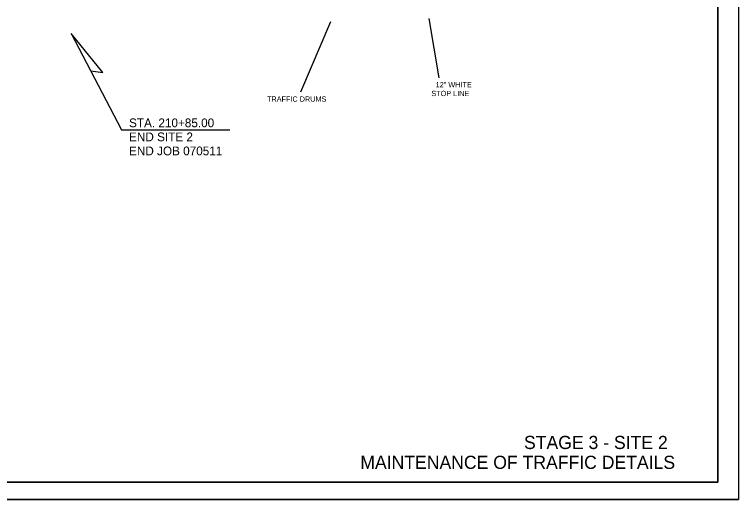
# Model space of a CAD drawing. Extents: x 1398460 to 1408037, y 380768 to 383968.
# Drawn here: x 1403174 to 1403999, y 380768 to 381320 of the extents above; entities that cross this region are included whole.
import ezdxf

# ---------------------------------------------------------------- set-up
doc = ezdxf.new("R2010")
doc.units = 0
for name, color, linetype in [('Default', 7, 'Continuous'), ('R_Border', 7, 'Continuous'), ('R_Dimension', 7, 'Continuous'), ('R_MOT', 7, 'Continuous'), ('R_No Plot', 7, 'Continuous')]:
    doc.layers.add(name, color=color, linetype=linetype)

msp = doc.modelspace()

# ---------------------------------------------------------------- linework, layer by layer
at = {"layer": 'Default'}
for p, q in [((1403238.3, 381298.9), (1403295.63, 381188.99)), ((1403295.63, 381188.99), (1403419.12, 381188.99))]:
    msp.add_line(p, q, dxfattribs=at)
msp.add_lwpolyline([(1403260.57, 381256.2), (1403274.18, 381254.22), (1403238.3, 381298.9)], dxfattribs=at)
at = {"layer": 'R_Border'}
for q in [(1403975.17, 381814.73), (1402394.27, 380787.43)]:
    msp.add_line((1403975.17, 380787.43), q, dxfattribs=at)
at = {"layer": 'R_Dimension'}
msp.add_line((1403500, 381232.17), (1403534.26, 381312.63), dxfattribs=at)
at = {"layer": 'R_MOT'}
msp.add_line((1403645.95, 381315.85), (1403657.28, 381248.21), dxfattribs=at)
at = {"layer": 'R_No Plot'}
msp.add_line((1402332.26, 380767.54), (1403998.93, 380767.54), dxfattribs=at)
for points in [[(1402332.23, 381834.2), (1403998.93, 381834.2), (1403998.93, 380767.52), (1402332.23, 380767.52)], [(1402394.27, 381814.73), (1402394.27, 380787.43), (1403975.17, 380787.43), (1403975.17, 381643.67), (1403858.52, 381643.67), (1403858.52, 381765.33), (1403661.97, 381765.33), (1403661.97, 381814.73)], [(1403563.87, 381814.73), (1403661.97, 381814.73), (1403661.97, 381765.33), (1403742.53, 381765.33), (1403858.52, 381765.33), (1403858.52, 381643.67), (1403975.17, 381643.67), (1403975.17, 380787.43), (1402394.27, 380787.43), (1402394.27, 381814.73)]]:
    msp.add_lwpolyline(points, close=True, dxfattribs=at)

# ---------------------------------------------------------------- texts
at = {"layer": 'Default'}
for s, p in [('12" WHITE', (1403653.67, 381237.37)), ('STOP LINE', (1403648.76, 381227.41))]:
    msp.add_text(s, height=6, rotation=0, dxfattribs=at).set_placement(p)
at = {"layer": 'R_Border'}
for s, height, p in [('TRAFFIC DRUMS', 6, (1403461.43, 381221.03)), ('STAGE 3 - SITE 2 ', 15, (1403754.38, 380825.07)), ('MAINTENANCE OF TRAFFIC DETAILS', 15, (1403567.77, 380802.43))]:
    msp.add_text(s, height=height, dxfattribs=at).set_placement(p)
at = {"layer": 'R_Dimension'}
for s, p in [('STA. 210+85.00', (1403304.16, 381191.91)), ('END SITE 2', (1403304.16, 381175.91)), ('END JOB 070511', (1403304.16, 381159.91))]:
    msp.add_text(s, height=10, dxfattribs=at).set_placement(p)

doc.saveas('drawing.dxf')
